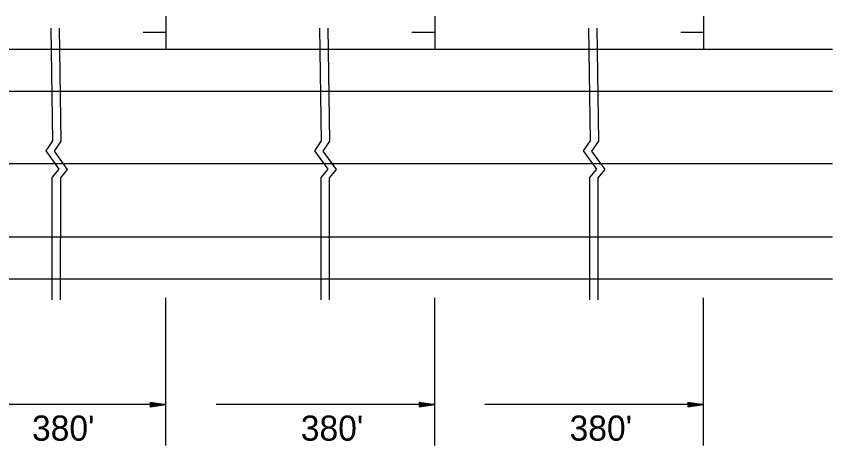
# Model space of a CAD drawing. Extents: x 1678017 to 1687792, y 404433 to 413488.
# Drawn here: x 1680795.5 to 1680990.3, y 404723.6 to 404826 of the extents above; entities that cross this region are included whole.
import ezdxf

# ---------------------------------------------------------------- set-up
doc = ezdxf.new("R2010")
doc.units = 0
doc.layers.add('Default', color=7, linetype='Continuous')

msp = doc.modelspace()

# ---------------------------------------------------------------- linework, layer by layer
at = {"layer": 'Default'}
for p, q in [((1680831.18, 404825.98), (1680831.18, 404818.15)), ((1680895.34, 404825.98), (1680895.34, 404818.15)), ((1680959.5, 404825.98), (1680959.5, 404818.15)), ((1680831.07, 404822.09), (1680825.73, 404822.09)), ((1680895.23, 404822.09), (1680889.89, 404822.09)), ((1680959.39, 404822.09), (1680954.05, 404822.09)), ((1680081.8, 404818.15), (1680990.32, 404818.15)), ((1680637.3, 404808.15), (1680990.32, 404808.15)), ((1680990.32, 404790.77), (1680548.11, 404790.77)), ((1680637.3, 404773.39), (1680990.32, 404773.39)), ((1680081.8, 404763.39), (1680990.32, 404763.39)), ((1680831.18, 404723.6), (1680831.18, 404758.81)), ((1680895.34, 404723.6), (1680895.34, 404758.81)), ((1680959.5, 404723.6), (1680959.5, 404758.81)), ((1680831.18, 404733.39), (1680778.99, 404733.39)), ((1680827.43, 404733.95), (1680831.18, 404733.39)), ((1680827.43, 404733.95), (1680827.43, 404732.83)), ((1680827.43, 404733.86), (1680830.56, 404733.39)), ((1680827.43, 404733.76), (1680829.91, 404733.39)), ((1680827.43, 404733.67), (1680829.29, 404733.39)), ((1680827.43, 404733.57), (1680828.65, 404733.39)), ((1680827.43, 404733.48), (1680828.03, 404733.39)), ((1680827.43, 404732.83), (1680831.18, 404733.39)), ((1680827.43, 404733.2), (1680828.65, 404733.39)), ((1680827.43, 404733.01), (1680829.91, 404733.39)), ((1680827.43, 404732.92), (1680830.56, 404733.39)), ((1680827.43, 404733.11), (1680829.29, 404733.39)), ((1680827.43, 404733.3), (1680828.03, 404733.39)), ((1680895.34, 404733.39), (1680843.16, 404733.39)), ((1680891.59, 404733.95), (1680895.34, 404733.39)), ((1680891.59, 404733.95), (1680891.59, 404732.83)), ((1680891.59, 404733.86), (1680894.72, 404733.39)), ((1680891.59, 404733.76), (1680894.07, 404733.39)), ((1680891.59, 404733.67), (1680893.45, 404733.39)), ((1680891.59, 404733.57), (1680892.81, 404733.39)), ((1680891.59, 404733.48), (1680892.19, 404733.39)), ((1680891.59, 404732.83), (1680895.34, 404733.39)), ((1680891.59, 404733.2), (1680892.81, 404733.39)), ((1680891.59, 404733.01), (1680894.07, 404733.39)), ((1680891.59, 404732.92), (1680894.72, 404733.39)), ((1680891.59, 404733.11), (1680893.45, 404733.39)), ((1680891.59, 404733.3), (1680892.19, 404733.39)), ((1680959.5, 404733.39), (1680907.32, 404733.39)), ((1680955.75, 404733.95), (1680959.5, 404733.39)), ((1680955.75, 404733.95), (1680955.75, 404732.83)), ((1680955.75, 404733.86), (1680958.88, 404733.39)), ((1680955.75, 404733.76), (1680958.23, 404733.39)), ((1680955.75, 404733.67), (1680957.61, 404733.39)), ((1680955.75, 404733.57), (1680956.97, 404733.39)), ((1680955.75, 404733.48), (1680956.35, 404733.39)), ((1680955.75, 404732.83), (1680959.5, 404733.39)), ((1680955.75, 404733.2), (1680956.97, 404733.39)), ((1680955.75, 404733.01), (1680958.23, 404733.39)), ((1680955.75, 404732.92), (1680958.88, 404733.39)), ((1680955.75, 404733.11), (1680957.61, 404733.39)), ((1680955.75, 404733.3), (1680956.35, 404733.39))]:
    msp.add_line(p, q, dxfattribs=at)
for points in [[(1680803.68, 404823.16), (1680804.09, 404796.28), (1680802.47, 404793.87), (1680805.63, 404789.54), (1680803.97, 404787.54), (1680803.96, 404758.39)], [(1680805.68, 404823.16), (1680806.09, 404796.2), (1680804.47, 404793.79), (1680807.63, 404789.46), (1680805.97, 404787.46), (1680805.96, 404758.39)], [(1680867.85, 404823.16), (1680868.25, 404796.28), (1680866.63, 404793.87), (1680869.79, 404789.54), (1680868.13, 404787.54), (1680868.12, 404758.39)], [(1680869.84, 404823.16), (1680870.25, 404796.2), (1680868.63, 404793.79), (1680871.79, 404789.46), (1680870.13, 404787.46), (1680870.12, 404758.39)], [(1680932.01, 404823.16), (1680932.42, 404796.28), (1680930.79, 404793.87), (1680933.96, 404789.54), (1680932.29, 404787.54), (1680932.28, 404758.39)], [(1680934, 404823.16), (1680934.41, 404796.2), (1680932.79, 404793.79), (1680935.95, 404789.46), (1680934.29, 404787.46), (1680934.28, 404758.39)]]:
    msp.add_lwpolyline(points, dxfattribs=at)

# ---------------------------------------------------------------- texts
for p in [(1680799.2, 404724.78), (1680863.36, 404724.78), (1680927.52, 404724.78)]:
    msp.add_text("380'", height=6, dxfattribs=at).set_placement(p)

doc.saveas('drawing.dxf')
